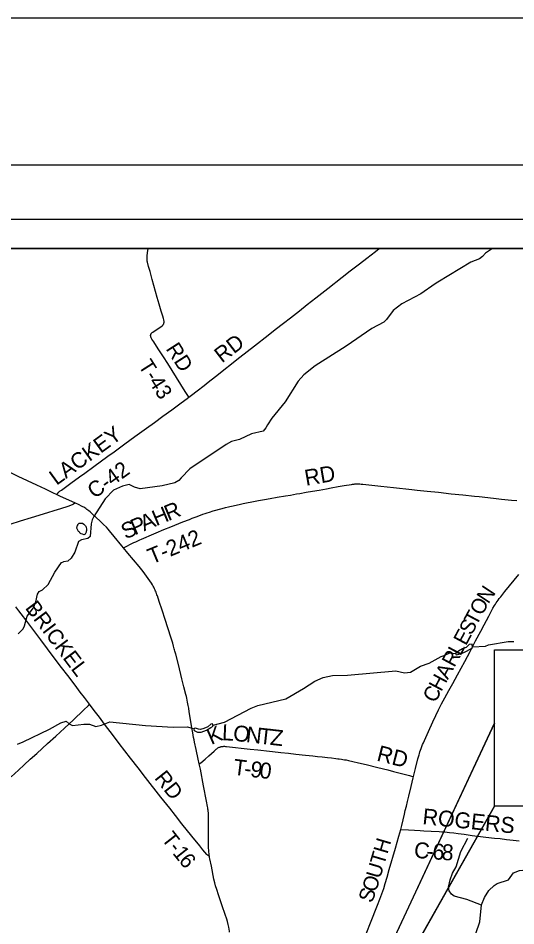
# Model space of a CAD drawing. Extents: x -13.9 to 69.1, y -25.2 to 26.1.
# Drawn here: x 3.383 to 5.08, y 18.903 to 22 of the extents above; entities that cross this region are included whole.
import ezdxf

# ---------------------------------------------------------------- set-up
doc = ezdxf.new("R2010")
doc.units = 0
for name, color, linetype in [('Default', 7, 'Continuous'), ('GM_X_County_Road', 7, 'Continuous'), ('GM_X_County_Road_Text', 7, 'Continuous'), ('GM_X_Major_River', 7, 'Continuous'), ('GM_X_Minor_Lake', 7, 'Continuous'), ('GM_X_Minor_River', 7, 'Continuous'), ('GM_X_State_Route', 7, 'Continuous'), ('GM_X_Township', 7, 'Continuous'), ('GM_X_Township_Road', 7, 'Continuous'), ('GM_X_Township_Road_Text', 7, 'Continuous'), ('SH_Border', 7, 'Continuous'), ('SH_Cut_Line', 7, 'Continuous'), ('SH_Data', 7, 'Continuous'), ('SH_Text', 7, 'Continuous')]:
    doc.layers.add(name, color=color, linetype=linetype)

msp = doc.modelspace()

# ---------------------------------------------------------------- linework, layer by layer
at = {"layer": 'Default'}
msp.add_lwpolyline([(5.0073, 19.3964), (5.0073, 19.7501)], dxfattribs=at)
at = {"layer": 'GM_X_County_Road'}
for points in [[(3.9656, 20.7067), (3.9741, 20.7133), (3.9937, 20.7288), (4.0169, 20.7471), (4.0313, 20.7585), (4.0556, 20.7777), (4.1393, 20.843), (4.1888, 20.882), (4.2353, 20.9184), (4.2599, 20.9376), (4.288, 20.9594), (4.3114, 20.9777), (4.3419, 21.0017), (4.3685, 21.0227), (4.3976, 21.0454), (4.4391, 21.078), (4.4877, 21.1163), (4.5149, 21.1376), (4.5468, 21.1623), (4.5714, 21.1815), (4.601, 21.2045), (4.6139, 21.2145)], [(3.5145, 20.3749), (3.5165, 20.3776), (3.5181, 20.3795), (3.5191, 20.3807), (3.5206, 20.3822), (3.5221, 20.3835), (3.5239, 20.3849), (3.5268, 20.3872), (3.5307, 20.3901), (3.5629, 20.4133), (3.5921, 20.4348), (3.6104, 20.4482), (3.641, 20.4705), (3.6896, 20.5058), (3.7102, 20.5207), (3.7468, 20.5474), (3.7812, 20.5723), (3.8205, 20.6011), (3.848, 20.621), (3.8763, 20.6418), (3.9069, 20.6642), (3.9391, 20.6873), (3.9597, 20.7023), (3.9656, 20.7067)], [(3.1987, 20.2246), (3.2075, 20.2273), (3.2707, 20.2469), (3.3115, 20.2598), (3.3566, 20.2741), (3.3911, 20.285), (3.4288, 20.2967), (3.4851, 20.3141), (3.5064, 20.3207), (3.5287, 20.3277), (3.5536, 20.3355), (3.5681, 20.3403), (3.5706, 20.3415), (3.5726, 20.3428), (3.577, 20.3461)], [(4.7307, 19.4125), (4.7374, 19.4401), (4.746, 19.4733), (4.7477, 19.48), (4.7496, 19.4865), (4.751, 19.4916), (4.7528, 19.4973), (4.7547, 19.5029), (4.7569, 19.509), (4.7591, 19.515), (4.7618, 19.5216), (4.7644, 19.5279), (4.7678, 19.5357), (4.7817, 19.5668), (4.7965, 19.5994), (4.8066, 19.6212), (4.8159, 19.6402), (4.8205, 19.6489), (4.8268, 19.6609), (4.8381, 19.6814), (4.8516, 19.7059), (4.8651, 19.7305), (4.8807, 19.7593), (4.8933, 19.783), (4.9053, 19.8051), (4.9237, 19.8397), (4.9426, 19.8753), (4.9603, 19.9089), (4.9719, 19.9306), (4.9873, 19.9595), (5.0018, 19.9869), (5.007, 19.9961), (5.0098, 20.0006), (5.0126, 20.0049), (5.0158, 20.0095), (5.0193, 20.0145), (5.0233, 20.0198), (5.0281, 20.0259), (5.0423, 20.0435), (5.0901, 20.1019)], [(3.36, 19.412), (3.3848, 19.4348), (3.404, 19.4527), (3.4247, 19.4716), (3.4466, 19.4915), (3.4837, 19.5255), (3.5116, 19.5508), (3.5412, 19.5775), (3.572, 19.6064), (3.6063, 19.6393), (3.6227, 19.6552), (3.6268, 19.6592)], [(4.6878, 19.2326), (4.691, 19.2462), (4.7001, 19.2841), (4.703, 19.2964), (4.7069, 19.3121), (4.7106, 19.3275), (4.7149, 19.3459), (4.7227, 19.3792), (4.7297, 19.4084), (4.7307, 19.4125)], [(4.5587, 18.8488), (4.5717, 18.8821), (4.5844, 18.9137), (4.6087, 18.9743), (4.6166, 18.9946), (4.623, 19.0123), (4.6292, 19.0308), (4.6346, 19.0483), (4.6407, 19.0699), (4.6483, 19.096), (4.6695, 19.1686), (4.6812, 19.2095), (4.6878, 19.2326)], [(4.6878, 19.2326), (4.7143, 19.2306), (4.734, 19.2294), (4.7531, 19.2283), (4.7657, 19.2277), (4.7913, 19.2265), (4.8183, 19.225), (4.8272, 19.2245), (4.8377, 19.2237), (4.8458, 19.2228), (4.8541, 19.222), (4.8688, 19.2202), (4.8835, 19.2184), (4.9034, 19.2158), (4.931, 19.212), (4.9591, 19.2084), (4.9776, 19.2062), (5.0065, 19.203), (5.0264, 19.2009), (5.0479, 19.1985), (5.0705, 19.196), (5.0906, 19.1935)]]:
    msp.add_lwpolyline(points, dxfattribs=at)
at = {"layer": 'GM_X_Major_River'}
msp.add_lwpolyline([(4.8397, 18.6945), (4.8672, 18.7259), (4.9208, 18.8058), (4.9317, 18.8321), (4.9358, 18.8538), (4.9422, 18.8675), (4.943, 18.8776), (4.9565, 18.917), (4.9627, 18.975), (4.9726, 19.0006), (4.9871, 19.0239), (5.0063, 19.0406), (5.0165, 19.0476), (5.0544, 19.0602), (5.0714, 19.0839), (5.0917, 19.0918), (5.1025, 19.0934), (5.124, 19.0911), (5.1581, 19.0773), (5.1695, 19.0737), (5.2352, 19.0599), (5.2439, 19.0561), (5.28, 19.027)], dxfattribs=at)
at = {"layer": 'GM_X_Minor_Lake'}
for points in [[(3.5889, 20.2493), (3.583, 20.2599), (3.5837, 20.2628), (3.584, 20.265), (3.5851, 20.2676), (3.5864, 20.2708), (3.5871, 20.2726), (3.5892, 20.2751), (3.5919, 20.2766), (3.5949, 20.2776), (3.5966, 20.2776), (3.5993, 20.2776), (3.6027, 20.2768), (3.6077, 20.2735), (3.6104, 20.2709), (3.6127, 20.2679), (3.6137, 20.2661), (3.6147, 20.2643), (3.6157, 20.2625), (3.6167, 20.2577), (3.6167, 20.2552), (3.6163, 20.2523), (3.6156, 20.2486), (3.6149, 20.2465), (3.6138, 20.2439), (3.6132, 20.2417), (3.6121, 20.2399), (3.6097, 20.2385), (3.608, 20.2378), (3.6027, 20.2397), (3.5986, 20.2405), (3.5963, 20.2416), (3.5946, 20.2423), (3.5933, 20.2449), (3.5913, 20.2471), (3.5889, 20.2489), (3.5889, 20.2493)], [(4.8762, 19.8278), (4.8945, 19.8329), (4.9074, 19.8381), (4.9264, 19.8487), (4.9319, 19.8526), (4.9304, 19.8642), (4.9209, 19.863), (4.9106, 19.8526), (4.8984, 19.8481), (4.8838, 19.8404), (4.8763, 19.8366)], [(4.8763, 19.8366), (4.8752, 19.8354), (4.8746, 19.8332), (4.875, 19.8297), (4.8762, 19.8278)], [(3.9884, 19.5779), (3.9869, 19.5784), (3.9852, 19.5776), (3.9831, 19.5759), (3.9825, 19.5731), (3.9832, 19.5703)], [(3.9832, 19.5703), (3.9946, 19.5639), (4.0077, 19.5644), (4.025, 19.5706), (4.04, 19.5798), (4.0485, 19.5851), (4.0463, 19.5927), (4.0399, 19.5914), (4.03, 19.5821), (4.0164, 19.5762), (4.0049, 19.5732), (3.9985, 19.5748), (3.9884, 19.5779)], [(4.8397, 18.6945), (4.8672, 18.7259), (4.9208, 18.8058), (4.9317, 18.8321), (4.9358, 18.8538), (4.9422, 18.8675), (4.943, 18.8776), (4.9565, 18.917), (4.9627, 18.975), (4.9726, 19.0006), (4.9871, 19.0239), (5.0063, 19.0406), (5.0165, 19.0476), (5.0544, 19.0602), (5.0714, 19.0839), (5.0917, 19.0918), (5.1025, 19.0934), (5.124, 19.0911), (5.1581, 19.0773), (5.1695, 19.0737), (5.2352, 19.0599), (5.2439, 19.0561), (5.28, 19.027)]]:
    msp.add_lwpolyline(points, dxfattribs=at)
at = {"layer": 'GM_X_Minor_River'}
for points in [[(5, 21.2145), (4.9767, 21.1987), (4.9661, 21.1873), (4.9558, 21.1791), (4.9263, 21.1681), (4.8143, 21.099), (4.8044, 21.0934), (4.7553, 21.0599), (4.691, 21.0251), (4.661, 21.0028), (4.6392, 20.972), (4.63, 20.9634), (4.5885, 20.941), (4.5018, 20.8809), (4.3952, 20.8143), (4.3566, 20.783), (4.3377, 20.7619), (4.2934, 20.6915), (4.248, 20.6357), (4.2334, 20.6127), (4.2275, 20.6027), (4.2189, 20.5912), (4.179, 20.5814), (4.1382, 20.5626), (4.1101, 20.5552), (4.0921, 20.545), (3.9683, 20.4623), (3.9385, 20.4323), (3.9306, 20.423), (3.9177, 20.4149), (3.874, 20.4041), (3.7993, 20.3943), (3.7805, 20.4005), (3.7618, 20.4089), (3.7385, 20.4039), (3.7082, 20.3892), (3.6798, 20.36), (3.6417, 20.2996), (3.6361, 20.2881), (3.6322, 20.2754), (3.6294, 20.2318), (3.6206, 20.2254), (3.5989, 20.2208), (3.589, 20.2144), (3.5766, 20.1779), (3.5641, 20.1578), (3.5532, 20.1471), (3.5375, 20.1454)], [(3.3832, 19.8992), (3.4003, 19.9168), (3.4055, 19.9265), (3.4147, 19.9602), (3.4357, 19.9882), (3.4434, 20.0084), (3.4499, 20.0352), (3.4554, 20.0446), (3.4659, 20.0499), (3.4854, 20.0674), (3.5083, 20.1096), (3.531, 20.143), (3.5375, 20.1454)], [(4.9315, 19.8553), (4.9765, 19.8579), (4.987, 19.862), (5.0536, 19.8731), (5.0728, 19.8731)], [(4.0477, 19.5879), (4.0872, 19.5981), (4.1777, 19.6466), (4.2001, 19.6548), (4.2952, 19.6774), (4.3558, 19.7133), (4.395, 19.738), (4.4225, 19.7509), (4.4553, 19.7572), (4.5055, 19.7584), (4.6706, 19.7729), (4.6999, 19.7669), (4.7205, 19.7691), (4.7545, 19.7888), (4.7843, 19.7998), (4.8252, 19.8219), (4.8357, 19.8257), (4.8544, 19.8352), (4.8747, 19.8325)], [(3.5285, 19.5964), (3.5475, 19.6014), (3.5568, 19.5922), (3.5682, 19.5865), (3.6074, 19.5919), (3.6269, 19.5912), (3.6477, 19.5838), (3.6676, 19.5882), (3.6958, 19.5989), (3.817, 19.5871), (3.9116, 19.5808), (3.9605, 19.5828), (3.9831, 19.5759)], [(3.3808, 19.5233), (3.4008, 19.5317), (3.4898, 19.5739), (3.5285, 19.5964)], [(4.9626, 18.9739), (4.9129, 18.9937), (4.8689, 19.0047), (4.8603, 19.0111), (4.8524, 19.0229), (4.8496, 19.0353), (4.8557, 19.0599), (4.8632, 19.0834), (4.876, 19.1043), (4.8917, 19.1571), (4.9164, 19.2024)]]:
    msp.add_lwpolyline(points, dxfattribs=at)
at = {"layer": 'GM_X_State_Route'}
for points in [[(4.0793, 18.9717), (4.0792, 18.972), (4.0665, 19.0088), (4.0604, 19.0273), (4.0565, 19.0403), (4.0537, 19.0505), (4.0509, 19.0626), (4.0419, 19.1074), (4.0369, 19.1324), (4.0361, 19.1361), (4.0354, 19.1403), (4.0348, 19.1447), (4.034, 19.1506), (4.0335, 19.1553), (4.0331, 19.1601), (4.0327, 19.1697), (4.0325, 19.1761), (4.0324, 19.1861), (4.0325, 19.225), (4.0323, 19.272), (4.0321, 19.2787), (4.0319, 19.2832), (4.0316, 19.2886), (4.031, 19.2945), (4.0306, 19.298), (4.0302, 19.3015), (4.0295, 19.306), (4.0288, 19.3103), (4.0256, 19.3283), (4.0155, 19.3814), (4.0045, 19.4384), (4.0009, 19.4557), (3.9974, 19.4721), (3.9902, 19.5045), (3.9844, 19.5305), (3.9828, 19.5382), (3.9812, 19.546), (3.9797, 19.5536), (3.9782, 19.5619), (3.9753, 19.5789), (3.9719, 19.6), (3.9667, 19.634), (3.9647, 19.6462), (3.9632, 19.6551), (3.9622, 19.6612), (3.9611, 19.6668), (3.9597, 19.6734), (3.9582, 19.68), (3.9568, 19.6862), (3.9553, 19.6921), (3.9483, 19.719), (3.9415, 19.746), (3.9295, 19.7949), (3.9208, 19.8299), (3.9178, 19.8409), (3.9168, 19.845), (3.9157, 19.8489), (3.9132, 19.8574), (3.9102, 19.8673), (3.9036, 19.8883), (3.8842, 19.9484), (3.874, 19.98), (3.8643, 20.0094), (3.858, 20.0288), (3.8566, 20.0332), (3.855, 20.0377), (3.8535, 20.0415), (3.852, 20.045), (3.8505, 20.0486), (3.8485, 20.0532), (3.8458, 20.0587), (3.8437, 20.0625), (3.8413, 20.0667), (3.8377, 20.0724), (3.8213, 20.0963), (3.8091, 20.1124), (3.7961, 20.1289), (3.7574, 20.1751), (3.7422, 20.1934), (3.7368, 20.1999), (3.711, 20.2318), (3.6948, 20.2513), (3.6903, 20.2565), (3.684, 20.2631), (3.6747, 20.2724), (3.6614, 20.2849), (3.6393, 20.3056), (3.6283, 20.3155), (3.6246, 20.3187), (3.6214, 20.3214), (3.6179, 20.324), (3.6141, 20.3267), (3.6103, 20.3293), (3.6071, 20.3313), (3.6036, 20.3333), (3.5998, 20.3354), (3.5918, 20.3393), (3.577, 20.3461), (3.5279, 20.3687), (3.5145, 20.3749), (3.5035, 20.38), (3.4762, 20.393), (3.4469, 20.407), (3.3836, 20.4366), (3.3492, 20.453)], [(4.1041, 18.8819), (4.1035, 18.8855), (4.1013, 18.899), (4.0995, 18.9078), (4.0968, 18.9187), (4.0947, 18.9262), (4.0894, 18.9425), (4.0793, 18.9717)]]:
    msp.add_lwpolyline(points, dxfattribs=at)
at = {"layer": 'GM_X_Township'}
msp.add_lwpolyline([(8.0976, 21.2145), (2.668, 21.2145), (2.5713, 21.1249), (2.5376, 21.0933), (2.5207, 21.0774), (2.9282, 20.5283), (2.3149, 19.9943), (2.3345, 19.9924), (2.4186, 19.989), (2.4692, 19.987), (2.5176, 19.987), (2.5995, 20.0118), (2.5714, 18.9023), (4.5288, 18.7816), (7.8661, 18.459), (7.9988, 20.0382), (8.0428, 20.5625)], close=True, dxfattribs=at)
at = {"layer": 'GM_X_Township_Road'}
for points in [[(3.9656, 20.7067), (3.9618, 20.7127), (3.953, 20.7264), (3.893, 20.8213), (3.8783, 20.8443), (3.8627, 20.8689), (3.8492, 20.8899), (3.8454, 20.8958), (3.8425, 20.9002), (3.8395, 20.905), (3.8381, 20.9073), (3.8371, 20.9093), (3.8364, 20.9106), (3.8359, 20.912), (3.8355, 20.9131), (3.8353, 20.9139), (3.8351, 20.9149), (3.835, 20.9161), (3.8349, 20.9174), (3.8349, 20.9185), (3.8351, 20.9198), (3.8353, 20.9208), (3.8355, 20.9214), (3.8357, 20.9219), (3.836, 20.9224), (3.8364, 20.9231), (3.8368, 20.9237), (3.8375, 20.9245), (3.8382, 20.9252), (3.8393, 20.9263), (3.8407, 20.9274), (3.8427, 20.9289), (3.8506, 20.9345), (3.8662, 20.9451), (3.874, 20.9505), (3.8756, 20.9517), (3.8768, 20.9529), (3.8776, 20.9538), (3.8782, 20.9547), (3.8788, 20.9557), (3.8794, 20.9568), (3.8799, 20.958), (3.8802, 20.9591), (3.8804, 20.9603), (3.8806, 20.9614), (3.8807, 20.9626), (3.8808, 20.9638), (3.8807, 20.9652), (3.8805, 20.9668), (3.8801, 20.969), (3.8799, 20.9703), (3.8796, 20.9713), (3.8786, 20.9755), (3.8764, 20.9829), (3.8713, 21.0005), (3.8642, 21.0248), (3.8577, 21.0475), (3.8404, 21.1084), (3.8328, 21.1352), (3.8276, 21.1533), (3.8251, 21.1625), (3.8244, 21.1652), (3.8239, 21.1676), (3.8234, 21.1704), (3.823, 21.1732), (3.8228, 21.176), (3.8227, 21.1789), (3.8228, 21.1819), (3.823, 21.1854), (3.8233, 21.1888), (3.8245, 21.1995), (3.8266, 21.2145)], [(3.7422, 20.1934), (3.747, 20.1958), (3.7558, 20.2002), (3.7638, 20.2041), (3.778, 20.2107), (3.7841, 20.2136), (3.7917, 20.2171), (3.7984, 20.22), (3.804, 20.2225), (3.8199, 20.2293), (3.8298, 20.2336), (3.8542, 20.2442), (3.8802, 20.2551), (3.9037, 20.265), (3.931, 20.276), (3.9443, 20.2812), (3.9669, 20.2902), (3.9765, 20.294), (3.9932, 20.3003), (4.013, 20.3077), (4.021, 20.3104), (4.0279, 20.3128), (4.0352, 20.3152), (4.048, 20.3191), (4.0785, 20.3276), (4.0903, 20.3306), (4.1005, 20.333), (4.1054, 20.3342), (4.1101, 20.3354), (4.1157, 20.3366), (4.1411, 20.342), (4.1505, 20.344), (4.1911, 20.3523), (4.2025, 20.3545), (4.2233, 20.3581), (4.2424, 20.3613), (4.2664, 20.3655), (4.2942, 20.3703), (4.3111, 20.3732), (4.3318, 20.3768), (4.3433, 20.3789), (4.3646, 20.3826), (4.3869, 20.3864), (4.4088, 20.3901), (4.4339, 20.3946), (4.4508, 20.3976), (4.4742, 20.4019), (4.495, 20.4054), (4.52, 20.4096), (4.5234, 20.4101), (4.5264, 20.4105), (4.5289, 20.4107), (4.531, 20.4109), (4.5331, 20.411), (4.5361, 20.411), (4.5393, 20.411), (4.5433, 20.4109), (4.5476, 20.4108), (4.5523, 20.4105), (4.5576, 20.4101), (4.5889, 20.4068), (4.6192, 20.4036), (4.6632, 20.3988), (4.7248, 20.3922), (4.7429, 20.3903), (4.777, 20.3865), (4.8161, 20.3824), (4.859, 20.3778), (4.8992, 20.3736), (4.9387, 20.3693), (4.9541, 20.3676), (4.9646, 20.3665), (4.9745, 20.3654), (5.0036, 20.3621), (5.0306, 20.3592), (5.0647, 20.356), (5.0832, 20.354)], [(3.6268, 19.6592), (3.6091, 19.6824), (3.5951, 19.7008), (3.5772, 19.7242), (3.5525, 19.7571), (3.5315, 19.7847), (3.5064, 19.8179), (3.4832, 19.849), (3.4607, 19.8792), (3.4371, 19.9106), (3.4131, 19.9425), (3.3939, 19.968), (3.3862, 19.9779), (3.3753, 19.9922)], [(4.0354, 19.1403), (4.0322, 19.1423), (4.0293, 19.1444), (4.0269, 19.1465), (4.0134, 19.163), (4.0029, 19.1761), (3.9756, 19.2097), (3.9417, 19.252), (3.9195, 19.2802), (3.9001, 19.3046), (3.8702, 19.3428), (3.8176, 19.4095), (3.792, 19.4422), (3.766, 19.4755), (3.747, 19.5002), (3.7278, 19.5256), (3.701, 19.5612), (3.6849, 19.5823), (3.6716, 19.5999), (3.6602, 19.6151), (3.6423, 19.6386), (3.6268, 19.6592)], [(4.0009, 19.4557), (4.0062, 19.4601), (4.0209, 19.4724), (4.0338, 19.4838), (4.051, 19.4996), (4.0561, 19.5042), (4.0584, 19.5061), (4.0606, 19.5078), (4.0629, 19.5095), (4.0645, 19.5104), (4.0668, 19.5116), (4.0688, 19.5126), (4.0711, 19.5135), (4.0734, 19.5142), (4.0747, 19.5145), (4.0758, 19.5148), (4.078, 19.5152), (4.0799, 19.5155), (4.0821, 19.5157), (4.0845, 19.5159), (4.087, 19.5159), (4.0899, 19.5158), (4.0934, 19.5156), (4.1043, 19.5145), (4.1247, 19.5118), (4.1434, 19.5096), (4.1742, 19.5064), (4.2003, 19.5037), (4.2396, 19.4991), (4.25, 19.498), (4.2792, 19.4949), (4.3045, 19.4921), (4.3298, 19.4891), (4.3632, 19.4854), (4.3748, 19.4842), (4.388, 19.4829), (4.4034, 19.4813), (4.4193, 19.4796), (4.4375, 19.4777), (4.4513, 19.4762), (4.4661, 19.4744), (4.4727, 19.4737), (4.4777, 19.473), (4.4853, 19.4719), (4.4898, 19.4713), (4.4952, 19.4703), (4.5008, 19.4693), (4.5088, 19.4676), (4.5246, 19.4642), (4.5429, 19.46), (4.5694, 19.4537), (4.6098, 19.4438), (4.6432, 19.4355), (4.6631, 19.4304), (4.7171, 19.4162), (4.7242, 19.4143), (4.7307, 19.4125)]]:
    msp.add_lwpolyline(points, dxfattribs=at)
at = {"layer": 'SH_Border'}
msp.add_lwpolyline([(1.5, 21.5), (33.5, 21.5), (33.5, 0.5), (1.5, 0.5)], close=True, dxfattribs=at)
at = {"layer": 'SH_Cut_Line'}
msp.add_lwpolyline([(0, 0), (34, 0), (34, 22), (0, 22)], close=True, dxfattribs=at)
at = {"layer": 'SH_Data'}
for p, q in [((1.6571, 21.3145), (8.6571, 21.3145)), ((1.7571, 21.2145), (8.5571, 21.2145))]:
    msp.add_line(p, q, dxfattribs=at)
at = {"layer": 'SH_Text'}
for p, q in [((4.2413, 17.9556), (5.0073, 19.5943)), ((5.0073, 19.3117), (4.2413, 17.9556))]:
    msp.add_line(p, q, dxfattribs=at)
for points in [[(5.0073, 19.8447), (6.8934, 19.8447), (6.8934, 19.3117), (5.0073, 19.3117)], [(5.0073, 19.5943), (4.2413, 17.9556), (5.0073, 19.3117)]]:
    msp.add_lwpolyline(points, close=True, dxfattribs=at)

# ---------------------------------------------------------------- texts
at = {"layer": 'GM_X_County_Road_Text'}
for s, height, rotation, p in [('RD', 0.0531, 37.6017, (4.0779, 20.8218)), ('LACKEY', 0.0532, 35.9853, (3.5142, 20.4043)), ('C-42', 0.05322, 35.7484, (3.6435, 20.3588)), ('N', 0.0519, 56.5377, (4.9858, 19.9993)), ('O', 0.0515, 61.7785, (4.9643, 19.959)), ('T', 0.0515, 61.8239, (4.9454, 19.9237)), ('S', 0.0515, 61.8192, (4.9284, 19.8919)), ('E', 0.0515, 61.8239, (4.9095, 19.8567)), ('L', 0.0515, 61.8239, (4.8906, 19.8214)), ('R', 0.0515, 61.8194, (4.8699, 19.7827)), ('A', 0.0515, 61.8212, (4.8477, 19.7413)), ('H', 0.0515, 61.8212, (4.8255, 19.6998)), ('C', 0.0515, 61.8213, (4.8047, 19.6611)), ('ROGERS', 0.05435, 354.1014, (4.7598, 19.2505)), ('H', 0.0509, 73.5825, (4.6419, 19.1464)), ('C', 0.0544, 354.5823, (4.7308, 19.1362)), ('6', 0.0544, 356.0538, (4.7942, 19.1307)), ('8', 0.0544, 356.2298, (4.8254, 19.1286)), ('T', 0.0509, 73.5874, (4.6305, 19.1076)), ('-', 0.0544, 356.0275, (4.7735, 19.1322)), ('U', 0.0509, 73.5725, (4.617, 19.062)), ('O', 0.0509, 72.6331, (4.6026, 19.0156)), ('S', 0.0511, 70.0053, (4.5892, 18.9788))]:
    msp.add_text(s, height=height, rotation=rotation, dxfattribs=at).set_placement(p)
at = {"layer": 'GM_X_Township_Road_Text'}
for s, height, rotation, p in [('RD', 0.05181, 302.7002, (3.885, 20.872)), ('T-43', 0.0518, 302.5424, (3.7914, 20.8147)), ('RD', 0.05429, 9.8221, (4.3645, 20.4044)), ('R', 0.0539, 22.6797, (3.8952, 20.2837)), ('H', 0.0539, 22.6887, (3.8538, 20.2664)), ('S', 0.0538, 25.0369, (3.7499, 20.2209)), ('P', 0.0539, 23.407, (3.7808, 20.2354)), ('A', 0.0539, 22.7351, (3.8123, 20.249)), ('T-242', 0.0539, 22.5596, (3.8387, 20.1361)), ('BRICKEL', 0.05209, 306.996, (3.4052, 19.9875)), ('K', 0.0539, 23.4946, (4.0415, 19.5199)), ('L', 0.0544, 357.2513, (4.0772, 19.5368)), ('O', 0.0543, 353.7809, (4.1142, 19.5351)), ('N', 0.0543, 353.7217, (4.1584, 19.5302)), ('T', 0.0543, 353.7214, (4.2027, 19.5254)), ('Z', 0.0543, 353.7257, (4.2403, 19.5212)), ('RD', 0.05418, 345.7035, (4.6027, 19.4677)), ('T', 0.0543, 352.9253, (4.1142, 19.4193)), ('9', 0.0543, 353.0679, (4.1726, 19.4121)), ('0', 0.0543, 353.6163, (4.204, 19.4083)), ('RD', 0.05218, 308.3827, (3.8458, 19.4073)), ('-', 0.0543, 352.953, (4.1518, 19.4147)), ('T', 0.0522, 308.1332, (3.8697, 19.1994)), ('-', 0.0522, 308.1813, (3.8941, 19.1682)), ('1', 0.0522, 308.4566, (3.9077, 19.151)), ('6', 0.0523, 309.4845, (3.9286, 19.1247))]:
    msp.add_text(s, height=height, rotation=rotation, dxfattribs=at).set_placement(p)

doc.saveas('drawing.dxf')
